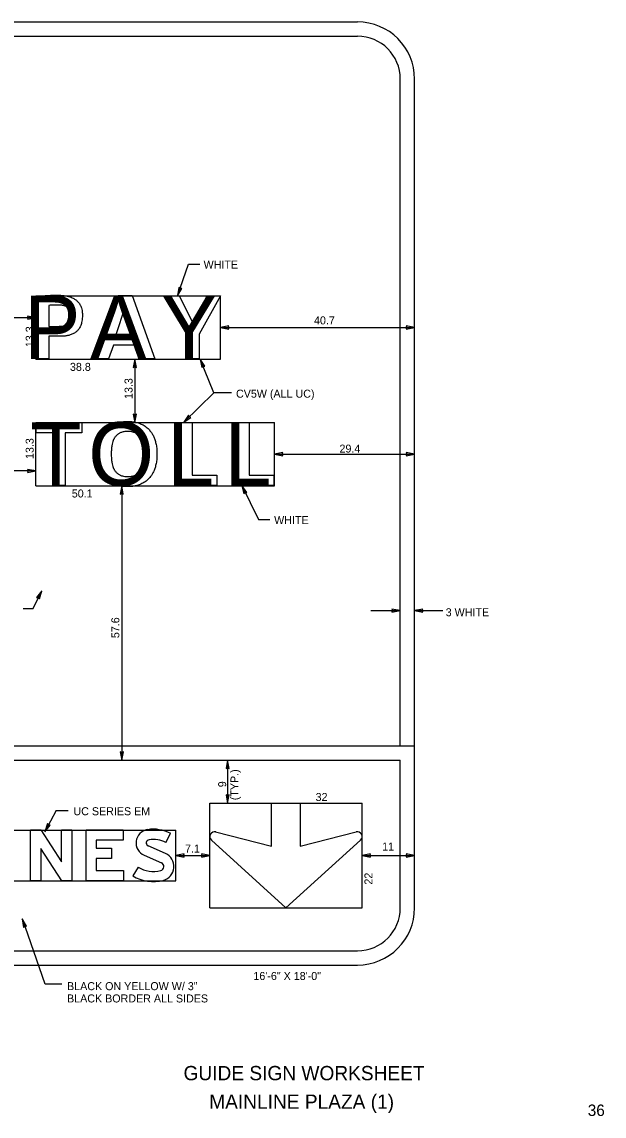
# Model space of a CAD drawing. Extents: x 319701 to 320014, y 1621790 to 1621996.
# Drawn here: x 319911.9 to 320013.7, y 1621795.1 to 1621986.5 of the extents above; entities that cross this region are included whole.
import ezdxf

# ---------------------------------------------------------------- set-up
doc = ezdxf.new("R2010")
doc.units = 0
for name, color, linetype in [('1', 7, 'Continuous'), ('48', 7, 'Continuous'), ('52', 7, 'Continuous'), ('GSBWFill', 7, 'Continuous'), ('GSColorFill', 7, 'Continuous'), ('GSOutline', 7, 'Continuous'), ('SOILS_SP83_SHP', 7, 'Continuous'), ('TextMisc', 7, 'Continuous'), ('TextShtNo', 7, 'Continuous')]:
    doc.layers.add(name, color=color, linetype=linetype)

msp = doc.modelspace()

# ---------------------------------------------------------------- linework, layer by layer
at = {"layer": '1'}
for p, q in [((319810.55, 1621986.54), (319970.55, 1621986.54)), ((319810.55, 1621984.04), (319970.55, 1621984.04)), ((319978.05, 1621859.87), (319978.05, 1621976.54)), ((319980.55, 1621831.54), (319980.55, 1621976.54)), ((319914.3, 1621938.62), (319946.63, 1621938.62)), ((319914.3, 1621927.54), (319914.3, 1621938.62)), ((319946.63, 1621927.54), (319946.63, 1621938.62)), ((319914.3, 1621927.54), (319946.63, 1621927.54)), ((319914.3, 1621905.37), (319914.3, 1621916.46)), ((319914.3, 1621916.46), (319956.05, 1621916.46)), ((319956.05, 1621905.37), (319956.05, 1621916.46)), ((319914.3, 1621905.37), (319956.05, 1621905.37)), ((319842.22, 1621859.87), (319980.55, 1621859.87)), ((319844.72, 1621857.37), (319978.05, 1621857.37)), ((319978.05, 1621831.54), (319978.05, 1621857.37)), ((319944.72, 1621831.54), (319944.72, 1621849.87)), ((319944.72, 1621849.87), (319971.39, 1621849.87)), ((319971.39, 1621831.54), (319971.39, 1621849.87)), ((319895.39, 1621845.16), (319938.8, 1621845.16)), ((319938.8, 1621836.27), (319938.8, 1621845.16)), ((319895.39, 1621836.27), (319938.8, 1621836.27)), ((319944.72, 1621831.54), (319971.39, 1621831.54)), ((319844.72, 1621824.04), (319970.55, 1621824.04)), ((319810.55, 1621821.54), (319970.55, 1621821.54))]:
    msp.add_line(p, q, dxfattribs=at)
for centre, radius, start, end in [((319970.55, 1621976.54), 10, 0, 90), ((319970.55, 1621976.54), 7.5, 0, 90), ((319970.55, 1621831.54), 10, 270, 360), ((319970.55, 1621831.54), 7.5, 270, 360)]:
    msp.add_arc(centre, radius, start, end, dxfattribs=at)
at = {"layer": '48'}
for p, q in [((319939.11, 1621938.62), (319940.99, 1621944.13)), ((319940.99, 1621944.13), (319943.02, 1621944.13)), ((319914.3, 1621934.78), (319901.8, 1621934.78)), ((319946.63, 1621933.08), (319980.55, 1621933.08)), ((319931.63, 1621927.54), (319931.63, 1621916.46)), ((319945.47, 1621921.65), (319943.06, 1621927.54)), ((319945.47, 1621921.65), (319940.18, 1621916.53)), ((319948.56, 1621921.65), (319945.47, 1621921.65)), ((319956.05, 1621910.92), (319980.55, 1621910.92)), ((319914.3, 1621907.98), (319901.8, 1621907.98)), ((319929.35, 1621905.37), (319929.35, 1621857.37)), ((319950.31, 1621905.42), (319953.26, 1621899.51)), ((319953.26, 1621899.51), (319955.22, 1621899.51)), ((319913.82, 1621883.92), (319915.36, 1621887.03)), ((319912.12, 1621883.92), (319913.82, 1621883.92)), ((319972.87, 1621883.55), (319978.05, 1621883.55)), ((319980.55, 1621883.55), (319985.48, 1621883.55)), ((319947.87, 1621849.87), (319947.87, 1621857.37)), ((319917.87, 1621848.59), (319915.91, 1621844.87)), ((319917.87, 1621848.59), (319919.94, 1621848.59)), ((319938.8, 1621840.71), (319944.72, 1621840.71)), ((319971.39, 1621840.71), (319980.55, 1621840.71)), ((319915.97, 1621818.18), (319911.97, 1621829.6)), ((319918.88, 1621818.18), (319915.97, 1621818.18))]:
    msp.add_line(p, q, dxfattribs=at)
at = {"layer": '52'}
for p, q in [((319939.32, 1621940.08), (319939.11, 1621938.62)), ((319939.11, 1621938.62), (319939.84, 1621939.9)), ((319939.54, 1621939.89), (319939.32, 1621940.08)), ((319939.84, 1621939.9), (319939.54, 1621939.89)), ((319914.29, 1621934.78), (319912.84, 1621935.06)), ((319912.84, 1621935.06), (319912.95, 1621934.78)), ((319912.95, 1621934.78), (319912.84, 1621934.51)), ((319912.84, 1621934.51), (319914.29, 1621934.78)), ((319948.08, 1621933.35), (319946.63, 1621933.08)), ((319946.63, 1621933.08), (319948.08, 1621932.8)), ((319947.97, 1621933.08), (319948.08, 1621933.35)), ((319948.08, 1621932.8), (319947.97, 1621933.08)), ((319980.55, 1621933.08), (319979.1, 1621933.36)), ((319979.1, 1621933.36), (319979.21, 1621933.08)), ((319979.21, 1621933.08), (319979.1, 1621932.81)), ((319979.1, 1621932.81), (319980.55, 1621933.08)), ((319931.63, 1621927.54), (319931.35, 1621926.09)), ((319931.9, 1621926.09), (319931.63, 1621927.54)), ((319943.06, 1621927.54), (319943.35, 1621926.09)), ((319943.86, 1621926.3), (319943.06, 1621927.54)), ((319931.35, 1621926.09), (319931.63, 1621926.2)), ((319931.63, 1621926.2), (319931.9, 1621926.09)), ((319943.35, 1621926.09), (319943.57, 1621926.3)), ((319943.57, 1621926.3), (319943.86, 1621926.3)), ((319931.63, 1621917.8), (319931.36, 1621917.91)), ((319931.36, 1621917.91), (319931.63, 1621916.46)), ((319931.63, 1621916.46), (319931.91, 1621917.91)), ((319931.91, 1621917.91), (319931.63, 1621917.8)), ((319941.03, 1621917.73), (319940.18, 1621916.53)), ((319941.14, 1621917.46), (319941.03, 1621917.73)), ((319940.18, 1621916.53), (319941.42, 1621917.34)), ((319941.42, 1621917.34), (319941.14, 1621917.46)), ((319957.5, 1621911.19), (319956.05, 1621910.92)), ((319956.05, 1621910.92), (319957.5, 1621910.64)), ((319957.39, 1621910.92), (319957.5, 1621911.19)), ((319957.5, 1621910.64), (319957.39, 1621910.92)), ((319980.55, 1621910.92), (319979.1, 1621911.2)), ((319979.1, 1621911.2), (319979.21, 1621910.92)), ((319979.21, 1621910.92), (319979.1, 1621910.65)), ((319979.1, 1621910.65), (319980.55, 1621910.92)), ((319914.29, 1621907.98), (319912.84, 1621908.26)), ((319912.84, 1621908.26), (319912.95, 1621907.98)), ((319912.95, 1621907.98), (319912.84, 1621907.71)), ((319912.84, 1621907.71), (319914.29, 1621907.98)), ((319929.34, 1621905.37), (319929.06, 1621903.92)), ((319929.61, 1621903.92), (319929.34, 1621905.37)), ((319950.31, 1621905.41), (319950.71, 1621903.99)), ((319951.2, 1621904.24), (319950.31, 1621905.41)), ((319929.06, 1621903.92), (319929.34, 1621904.03)), ((319929.34, 1621904.03), (319929.61, 1621903.92)), ((319950.71, 1621903.99), (319950.91, 1621904.21)), ((319950.91, 1621904.21), (319951.2, 1621904.24)), ((319915.35, 1621887.03), (319914.45, 1621885.86)), ((319914.95, 1621885.62), (319915.35, 1621887.03)), ((319914.45, 1621885.86), (319914.75, 1621885.83)), ((319914.75, 1621885.83), (319914.95, 1621885.62)), ((319978.03, 1621883.54), (319976.58, 1621883.82)), ((319976.58, 1621883.82), (319976.69, 1621883.54)), ((319976.69, 1621883.54), (319976.58, 1621883.27)), ((319976.58, 1621883.27), (319978.03, 1621883.54)), ((319981.98, 1621883.81), (319980.53, 1621883.54)), ((319980.53, 1621883.54), (319981.98, 1621883.26)), ((319981.87, 1621883.54), (319981.98, 1621883.81)), ((319981.98, 1621883.26), (319981.87, 1621883.54)), ((319929.35, 1621858.71), (319929.08, 1621858.82)), ((319929.08, 1621858.82), (319929.35, 1621857.37)), ((319929.35, 1621857.37), (319929.63, 1621858.82)), ((319929.63, 1621858.82), (319929.35, 1621858.71)), ((319947.85, 1621857.37), (319947.57, 1621855.92)), ((319948.12, 1621855.92), (319947.85, 1621857.37)), ((319947.57, 1621855.92), (319947.85, 1621856.03)), ((319947.85, 1621856.03), (319948.12, 1621855.92)), ((319947.85, 1621851.21), (319947.58, 1621851.32)), ((319947.58, 1621851.32), (319947.85, 1621849.87)), ((319947.85, 1621849.87), (319948.13, 1621851.32)), ((319948.13, 1621851.32), (319947.85, 1621851.21)), ((319916.35, 1621846.28), (319915.91, 1621844.87)), ((319915.91, 1621844.87), (319916.84, 1621846.02)), ((319916.54, 1621846.06), (319916.35, 1621846.28)), ((319916.84, 1621846.02), (319916.54, 1621846.06)), ((319940.25, 1621840.98), (319938.8, 1621840.71)), ((319938.8, 1621840.71), (319940.25, 1621840.43)), ((319940.14, 1621840.71), (319940.25, 1621840.98)), ((319940.25, 1621840.43), (319940.14, 1621840.71)), ((319944.72, 1621840.71), (319943.27, 1621840.99)), ((319943.27, 1621840.99), (319943.38, 1621840.71)), ((319943.38, 1621840.71), (319943.27, 1621840.44)), ((319943.27, 1621840.44), (319944.72, 1621840.71)), ((319972.82, 1621840.98), (319971.37, 1621840.71)), ((319971.37, 1621840.71), (319972.82, 1621840.43)), ((319972.71, 1621840.71), (319972.82, 1621840.98)), ((319972.82, 1621840.43), (319972.71, 1621840.71)), ((319980.55, 1621840.71), (319979.1, 1621840.99)), ((319979.1, 1621840.99), (319979.21, 1621840.71)), ((319979.21, 1621840.71), (319979.1, 1621840.44)), ((319979.1, 1621840.44), (319980.55, 1621840.71)), ((319911.95, 1621829.6), (319912.17, 1621828.14)), ((319912.69, 1621828.32), (319911.95, 1621829.6)), ((319912.17, 1621828.14), (319912.4, 1621828.33)), ((319912.4, 1621828.33), (319912.69, 1621828.32))]:
    msp.add_line(p, q, dxfattribs=at)
at = {"layer": 'GSBWFill'}
for p, q in [((319937.05, 1621842.98), (319937.89, 1621844.55)), ((319936.98, 1621841.05), (319933.97, 1621842.37)), ((319933.25, 1621840.74), (319936.26, 1621839.42)), ((319932.19, 1621838.67), (319931.27, 1621837.15))]:
    msp.add_line(p, q, dxfattribs=at)
for points in [[(319913.39, 1621845.19), (319915.17, 1621845.19), (319918.82, 1621839.58), (319918.82, 1621845.19), (319920.6, 1621845.19), (319920.6, 1621836.29), (319918.84, 1621836.29), (319915.17, 1621841.93), (319915.17, 1621836.29), (319913.39, 1621836.29)], [(319929.58, 1621845.19), (319929.58, 1621843.41), (319924.86, 1621843.41), (319924.86, 1621841.99), (319927.53, 1621841.99), (319927.53, 1621840.21), (319924.86, 1621840.21), (319924.86, 1621838.07), (319929.67, 1621838.07), (319929.67, 1621836.29), (319923.09, 1621836.29), (319923.09, 1621845.19)]]:
    msp.add_lwpolyline(points, close=True, dxfattribs=at)
for centre, radius, start, end in [((319934.2, 1621842.9), 2.36, 99.4877, 246.3243), ((319934.87, 1621838.91), 6.4, 61.8214, 99.4877), ((319934.2, 1621842.9), 0.578, 99.4877, 246.3243), ((319934.87, 1621838.91), 4.62, 61.8214, 99.4877), ((319935.98, 1621838.77), 0.711, 284.4775, 66.3243), ((319935.98, 1621838.77), 2.49, 284.4775, 66.3243), ((319934.87, 1621843.07), 5.16, 238.7193, 284.4775), ((319934.87, 1621843.07), 6.94, 238.7193, 284.4775)]:
    msp.add_arc(centre, radius, start, end, dxfattribs=at)
at = {"layer": 'GSColorFill'}
for p, q in [((319937.05, 1621842.98), (319937.89, 1621844.55)), ((319936.98, 1621841.05), (319933.97, 1621842.37)), ((319933.25, 1621840.74), (319936.26, 1621839.42)), ((319932.19, 1621838.67), (319931.27, 1621837.15))]:
    msp.add_line(p, q, dxfattribs=at)
for points in [[(319913.39, 1621845.19), (319915.17, 1621845.19), (319918.82, 1621839.58), (319918.82, 1621845.19), (319920.6, 1621845.19), (319920.6, 1621836.29), (319918.84, 1621836.29), (319915.17, 1621841.93), (319915.17, 1621836.29), (319913.39, 1621836.29)], [(319929.58, 1621845.19), (319929.58, 1621843.41), (319924.86, 1621843.41), (319924.86, 1621841.99), (319927.53, 1621841.99), (319927.53, 1621840.21), (319924.86, 1621840.21), (319924.86, 1621838.07), (319929.67, 1621838.07), (319929.67, 1621836.29), (319923.09, 1621836.29), (319923.09, 1621845.19)]]:
    msp.add_lwpolyline(points, close=True, dxfattribs=at)
for centre, radius, start, end in [((319934.2, 1621842.9), 2.36, 99.4877, 246.3243), ((319934.87, 1621838.91), 6.4, 61.8214, 99.4877), ((319934.2, 1621842.9), 0.578, 99.4877, 246.3243), ((319934.87, 1621838.91), 4.62, 61.8214, 99.4877), ((319935.98, 1621838.77), 0.711, 284.4775, 66.3243), ((319935.98, 1621838.77), 2.49, 284.4775, 66.3243), ((319934.87, 1621843.07), 5.16, 238.7193, 284.4775), ((319934.87, 1621843.07), 6.94, 238.7193, 284.4775)]:
    msp.add_arc(centre, radius, start, end, dxfattribs=at)
at = {"layer": 'GSOutline'}
for p, q in [((319937.05, 1621842.98), (319937.89, 1621844.55)), ((319936.98, 1621841.05), (319933.97, 1621842.37)), ((319933.25, 1621840.74), (319936.26, 1621839.42)), ((319932.19, 1621838.67), (319931.27, 1621837.15))]:
    msp.add_line(p, q, dxfattribs=at)
for points in [[(319918.68, 1621931.55), (319916.6, 1621931.55), (319916.6, 1621927.58), (319914.45, 1621927.58), (319914.45, 1621938.54)], [(319916.6, 1621936.95), (319916.6, 1621933.28), (319918.26, 1621933.28)], [(319932.86, 1621927.58), (319931.99, 1621930), (319927.88, 1621930), (319927.03, 1621927.58), (319924.78, 1621927.58), (319928.72, 1621938.66), (319931.15, 1621938.66), (319935.15, 1621927.58), (319932.86, 1621927.58)], [(319942.86, 1621931.89), (319942.86, 1621927.58), (319940.71, 1621927.58), (319940.71, 1621931.83), (319936.93, 1621938.62), (319939.36, 1621938.62), (319941.81, 1621933.75), (319944.27, 1621938.62), (319946.62, 1621938.62), (319942.86, 1621931.89)], [(319929.95, 1621936.59), (319929.89, 1621936.59), (319928.33, 1621931.77), (319931.5, 1621931.77), (319929.95, 1621936.59)], [(319919.45, 1621914.63), (319919.45, 1621905.43), (319917.29, 1621905.43), (319917.29, 1621914.63), (319914.39, 1621914.63), (319914.39, 1621916.47), (319922.36, 1621916.47), (319922.36, 1621914.63), (319919.45, 1621914.63)], [(319939.48, 1621905.43), (319939.48, 1621916.47), (319941.63, 1621916.47), (319941.63, 1621907.25), (319945.95, 1621907.25), (319945.95, 1621905.43), (319939.48, 1621905.43)], [(319949.49, 1621905.43), (319949.49, 1621916.47), (319951.64, 1621916.47), (319951.64, 1621907.25), (319955.96, 1621907.25), (319955.96, 1621905.43), (319949.49, 1621905.43)]]:
    msp.add_lwpolyline(points, dxfattribs=at)
for points in [[(319913.39, 1621845.19), (319915.17, 1621845.19), (319918.82, 1621839.58), (319918.82, 1621845.19), (319920.6, 1621845.19), (319920.6, 1621836.29), (319918.84, 1621836.29), (319915.17, 1621841.93), (319915.17, 1621836.29), (319913.39, 1621836.29)], [(319929.58, 1621845.19), (319929.58, 1621843.41), (319924.86, 1621843.41), (319924.86, 1621841.99), (319927.53, 1621841.99), (319927.53, 1621840.21), (319924.86, 1621840.21), (319924.86, 1621838.07), (319929.67, 1621838.07), (319929.67, 1621836.29), (319923.09, 1621836.29), (319923.09, 1621845.19)]]:
    msp.add_lwpolyline(points, close=True, dxfattribs=at)
for centre, radius, start, end in [((319934.2, 1621842.9), 2.36, 99.4877, 246.3243), ((319934.87, 1621838.91), 6.4, 61.8214, 99.4877), ((319934.2, 1621842.9), 0.578, 99.4877, 246.3243), ((319934.87, 1621838.91), 4.62, 61.8214, 99.4877), ((319935.98, 1621838.77), 0.711, 284.4775, 66.3243), ((319935.98, 1621838.77), 2.49, 284.4775, 66.3243), ((319934.87, 1621843.07), 5.16, 238.7193, 284.4775), ((319934.87, 1621843.07), 6.94, 238.7193, 284.4775)]:
    msp.add_arc(centre, radius, start, end, dxfattribs=at)
for points in [[(319914.45, 1621938.54), (319914.72, 1621938.56), (319915.28, 1621938.62), (319916.17, 1621938.67), (319917.13, 1621938.72), (319917.79, 1621938.72), (319918.12, 1621938.73)], [(319918.12, 1621938.73), (319918.27, 1621938.72), (319918.7, 1621938.72), (319919.27, 1621938.66), (319919.81, 1621938.57), (319920.26, 1621938.45), (319920.67, 1621938.3), (319921, 1621938.12), (319921.2, 1621937.99), (319921.39, 1621937.85), (319921.61, 1621937.65), (319921.85, 1621937.37), (319922.01, 1621937.12), (319922.13, 1621936.9), (319922.24, 1621936.67), (319922.34, 1621936.34), (319922.44, 1621935.83), (319922.46, 1621935.44), (319922.46, 1621935.2)], [(319918.18, 1621937.01), (319918.06, 1621937.01), (319917.8, 1621937.01), (319917.42, 1621936.99), (319917.02, 1621936.97), (319916.74, 1621936.96), (319916.6, 1621936.95)], [(319920.29, 1621935.15), (319920.29, 1621935.23), (319920.29, 1621935.47), (319920.25, 1621935.76), (319920.19, 1621936), (319920.14, 1621936.15), (319920.08, 1621936.28), (319919.99, 1621936.42), (319919.9, 1621936.53), (319919.82, 1621936.6), (319919.73, 1621936.68), (319919.6, 1621936.75), (319919.44, 1621936.83), (319919.29, 1621936.88), (319919.12, 1621936.92), (319918.86, 1621936.97), (319918.53, 1621937), (319918.27, 1621937.01), (319918.18, 1621937.01)], [(319918.26, 1621933.28), (319918.41, 1621933.28), (319918.69, 1621933.28), (319919.01, 1621933.32), (319919.23, 1621933.35), (319919.37, 1621933.39), (319919.53, 1621933.45), (319919.66, 1621933.52), (319919.75, 1621933.58), (319919.84, 1621933.64), (319919.94, 1621933.74), (319920.04, 1621933.89), (319920.11, 1621934.02), (319920.15, 1621934.14), (319920.2, 1621934.28), (319920.25, 1621934.51), (319920.29, 1621934.82), (319920.29, 1621935.05), (319920.29, 1621935.15)], [(319922.46, 1621935.2), (319922.46, 1621935.06), (319922.45, 1621934.67), (319922.38, 1621934.15), (319922.27, 1621933.73), (319922.18, 1621933.45), (319922.06, 1621933.19), (319921.89, 1621932.9), (319921.72, 1621932.68), (319921.58, 1621932.52), (319921.42, 1621932.36), (319921.2, 1621932.19), (319920.9, 1621932.01), (319920.63, 1621931.88), (319920.34, 1621931.77), (319919.87, 1621931.64), (319919.29, 1621931.56), (319918.84, 1621931.55), (319918.68, 1621931.55)], [(319925.24, 1621910.96), (319925.24, 1621911.18), (319925.25, 1621911.8), (319925.37, 1621912.61), (319925.57, 1621913.36), (319925.73, 1621913.79), (319925.91, 1621914.19), (319926.12, 1621914.56), (319926.37, 1621914.9), (319926.58, 1621915.15), (319926.81, 1621915.39), (319927.12, 1621915.66), (319927.52, 1621915.94), (319927.89, 1621916.13), (319928.2, 1621916.26), (319928.53, 1621916.38), (319929.05, 1621916.53), (319929.7, 1621916.63), (319930.18, 1621916.64), (319930.38, 1621916.64)], [(319930.38, 1621916.64), (319930.58, 1621916.64), (319931.06, 1621916.63), (319931.71, 1621916.53), (319932.23, 1621916.38), (319932.56, 1621916.26), (319932.87, 1621916.13), (319933.24, 1621915.94), (319933.64, 1621915.66), (319933.95, 1621915.39), (319934.17, 1621915.15), (319934.38, 1621914.9), (319934.67, 1621914.49), (319934.95, 1621913.95), (319935.17, 1621913.36), (319935.37, 1621912.61), (319935.49, 1621911.8), (319935.5, 1621911.18), (319935.5, 1621910.96)], [(319930.37, 1621914.88), (319930.24, 1621914.88), (319930.04, 1621914.88), (319929.72, 1621914.84), (319929.43, 1621914.78), (319929.16, 1621914.69), (319928.97, 1621914.6), (319928.79, 1621914.5), (319928.59, 1621914.36), (319928.36, 1621914.15), (319928.21, 1621913.96), (319928.09, 1621913.79), (319927.99, 1621913.61), (319927.85, 1621913.32), (319927.72, 1621912.95), (319927.6, 1621912.42), (319927.52, 1621911.77), (319927.51, 1621911.23), (319927.5, 1621910.95)], [(319933.25, 1621910.95), (319933.24, 1621911.23), (319933.23, 1621911.77), (319933.15, 1621912.42), (319933.03, 1621912.95), (319932.91, 1621913.32), (319932.76, 1621913.61), (319932.66, 1621913.79), (319932.55, 1621913.96), (319932.39, 1621914.15), (319932.16, 1621914.36), (319931.96, 1621914.5), (319931.78, 1621914.6), (319931.58, 1621914.69), (319931.31, 1621914.78), (319930.89, 1621914.87), (319930.57, 1621914.88), (319930.37, 1621914.88)], [(319930.38, 1621905.24), (319930.18, 1621905.24), (319929.71, 1621905.25), (319929.06, 1621905.35), (319928.54, 1621905.5), (319928.21, 1621905.62), (319927.9, 1621905.75), (319927.53, 1621905.94), (319927.13, 1621906.22), (319926.82, 1621906.49), (319926.59, 1621906.73), (319926.38, 1621906.98), (319926.13, 1621907.32), (319925.83, 1621907.85), (319925.6, 1621908.44), (319925.37, 1621909.28), (319925.25, 1621910.1), (319925.24, 1621910.73), (319925.24, 1621910.96)], [(319927.5, 1621910.95), (319927.51, 1621910.67), (319927.52, 1621910.13), (319927.6, 1621909.48), (319927.72, 1621908.95), (319927.85, 1621908.57), (319927.99, 1621908.28), (319928.09, 1621908.1), (319928.21, 1621907.93), (319928.37, 1621907.74), (319928.59, 1621907.54), (319928.8, 1621907.39), (319928.98, 1621907.29), (319929.17, 1621907.2), (319929.44, 1621907.11), (319929.86, 1621907.03), (319930.18, 1621907.01), (319930.38, 1621907.01)], [(319935.5, 1621910.96), (319935.5, 1621910.73), (319935.49, 1621910.1), (319935.37, 1621909.28), (319935.16, 1621908.53), (319934.94, 1621907.93), (319934.66, 1621907.39), (319934.37, 1621906.98), (319934.15, 1621906.73), (319933.93, 1621906.49), (319933.62, 1621906.22), (319933.22, 1621905.94), (319932.85, 1621905.75), (319932.54, 1621905.62), (319932.22, 1621905.5), (319931.7, 1621905.35), (319931.05, 1621905.25), (319930.58, 1621905.24), (319930.38, 1621905.24)], [(319930.38, 1621907.01), (319930.52, 1621907.01), (319930.71, 1621907.02), (319931.03, 1621907.05), (319931.31, 1621907.11), (319931.58, 1621907.2), (319931.78, 1621907.29), (319931.96, 1621907.39), (319932.16, 1621907.54), (319932.39, 1621907.74), (319932.55, 1621907.94), (319932.66, 1621908.11), (319932.76, 1621908.29), (319932.91, 1621908.58), (319933.03, 1621908.96), (319933.15, 1621909.49), (319933.23, 1621910.14), (319933.24, 1621910.67), (319933.25, 1621910.95)]]:
    msp.add_open_spline(points, degree=3, dxfattribs=at)
at = {"layer": 'SOILS_SP83_SHP'}
for p, q in [((319955.55, 1621842.35), (319955.55, 1621849.85)), ((319955.55, 1621849.85), (319960.54, 1621849.85)), ((319960.54, 1621849.85), (319960.54, 1621842.35)), ((319958.04, 1621831.54), (319945.01, 1621843.4)), ((319945.76, 1621844.83), (319955.55, 1621842.35)), ((319971.09, 1621843.4), (319958.04, 1621831.54)), ((319960.54, 1621842.35), (319970.33, 1621844.83))]:
    msp.add_line(p, q, dxfattribs=at)
for centre, start, end in [((319945.58, 1621844.02), 75.8248, 227.7118), ((319970.54, 1621844.02), 312.2846, 104.1718)]:
    msp.add_arc(centre, 0.832, start, end, dxfattribs=at)

# ---------------------------------------------------------------- texts
at = {"layer": '48'}
for s, p in [('WHITE', (319943.65, 1621943.38)), ('40.7', (319962.96, 1621933.62)), ('38.8', (319920.28, 1621925.49)), ('CV5W (ALL UC)', (319949.32, 1621920.8)), ('29.4', (319967.42, 1621911.19)), ('50.1', (319920.6, 1621903.34)), ('WHITE', (319955.99, 1621898.69)), ('3 WHITE', (319985.99, 1621882.56)), ('32', (319963.24, 1621850.24)), ('UC SERIES EM', (319920.89, 1621847.75)), ('7.1', (319940.4, 1621841.21)), ('11', (319974.88, 1621841.58)), ('16\'-6" X 18\'-0"', (319952.36, 1621818.93)), ('BLACK ON YELLOW W/ 3"', (319919.77, 1621817.15)), ('BLACK BORDER ALL SIDES', (319919.77, 1621815))]:
    msp.add_text(s, height=1.4, dxfattribs=at).set_placement(p)
for s, p in [('13.3', (319913.94, 1621929.64)), ('13.3', (319931.23, 1621920.57)), ('13.3', (319913.93, 1621910.07)), ('57.6', (319928.91, 1621878.73)), ('(TYP.)', (319949.75, 1621850.38)), ('9', (319947.6, 1621852.65)), ('22', (319973.18, 1621835.61))]:
    msp.add_text(s, height=1.4, rotation=90, dxfattribs=at).set_placement(p)
at = {"layer": 'GSBWFill'}
for s, p in [('P', (319912.24, 1621927.58)), ('A', (319923.79, 1621927.58)), ('Y', (319936.15, 1621927.58)), ('T', (319913.28, 1621905.43)), ('O', (319923.47, 1621905.43)), ('L', (319937.26, 1621905.43)), ('L', (319947.28, 1621905.43))]:
    msp.add_text(s, height=11.08, dxfattribs=at).set_placement(p)
at = {"layer": 'GSColorFill'}
for s, p in [('P', (319912.24, 1621927.58)), ('A', (319923.79, 1621927.58)), ('Y', (319936.15, 1621927.58)), ('T', (319913.28, 1621905.43)), ('O', (319923.47, 1621905.43)), ('L', (319937.26, 1621905.43)), ('L', (319947.28, 1621905.43))]:
    msp.add_text(s, height=11.08, dxfattribs=at).set_placement(p)
at = {"layer": 'TextMisc'}
for s, p in [('  GUIDE SIGN WORKSHEET  ', (319938.28, 1621801.39)), ('   MAINLINE PLAZA (1)   ', (319941.85, 1621796.39))]:
    msp.add_text(s, height=2.5, rotation=360, dxfattribs=at).set_placement(p)
at = {"layer": 'TextShtNo'}
msp.add_text('36', height=2, rotation=360, dxfattribs=at).set_placement((320010.84, 1621795.14))

doc.saveas('drawing.dxf')
